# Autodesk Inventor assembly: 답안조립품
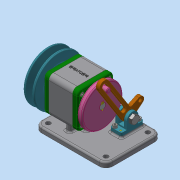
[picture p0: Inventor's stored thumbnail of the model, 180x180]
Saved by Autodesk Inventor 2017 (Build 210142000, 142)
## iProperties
Part Number: 답안조립품
Material: 일반
Document SubType Name: Assembly
Designer: mrc
Author: mrc
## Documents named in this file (19)
- C:\Users\mrc\Desktop\601106V1033\답안조립품.iam
- C:\Users\mrc\Desktop\601106V1033\본체.ipt
- C:\Users\mrc\Desktop\601106V1033\V-벨트풀리.ipt
- C:\Users\mrc\Desktop\601106V1033\너트 M8.ipt
- C:\Users\mrc\Desktop\601106V1033\너트 M10x1.ipt
- C:\Users\mrc\Desktop\601106V1033\돌림판.ipt
- C:\Users\mrc\Desktop\601106V1033\멈춤나사 M3x5.ipt
- C:\Users\mrc\Desktop\601106V1033\베어링 6004.ipt
- C:\Users\mrc\Desktop\601106V1033\볼트 M4.ipt
- C:\Users\mrc\Desktop\601106V1033\오일 실 17 30 5.ipt
- C:\Users\mrc\Desktop\601106V1033\와셔 8x15.5.ipt
- C:\Users\mrc\Desktop\601106V1033\축.ipt
- C:\Users\mrc\Desktop\601106V1033\커버.ipt
- C:\Users\mrc\Desktop\601106V1033\크랭크.ipt
- C:\Users\mrc\Desktop\601106V1033\키 4 x 4 x 8.ipt
- C:\Users\mrc\Desktop\601106V1033\키 5 x 5 x 12.ipt
- C:\Users\mrc\Desktop\601106V1033\핀 3 x 8.ipt
- C:\Users\mrc\Desktop\601106V1033\힌지 축.ipt
- C:\Users\mrc\Desktop\601106V1033\힌지.ipt
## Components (3 placed, 2 different names)
1. V-벨트풀리:1
2. 핀 3 x 8:1 — 플러쉬:2
3. 핀 3 x 8:2 — 플러쉬:3
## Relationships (2: Flush 2)
- 플러쉬:2 [Flush]: 핀 3 x 8:1
- 플러쉬:3 [Flush]: 핀 3 x 8:2
